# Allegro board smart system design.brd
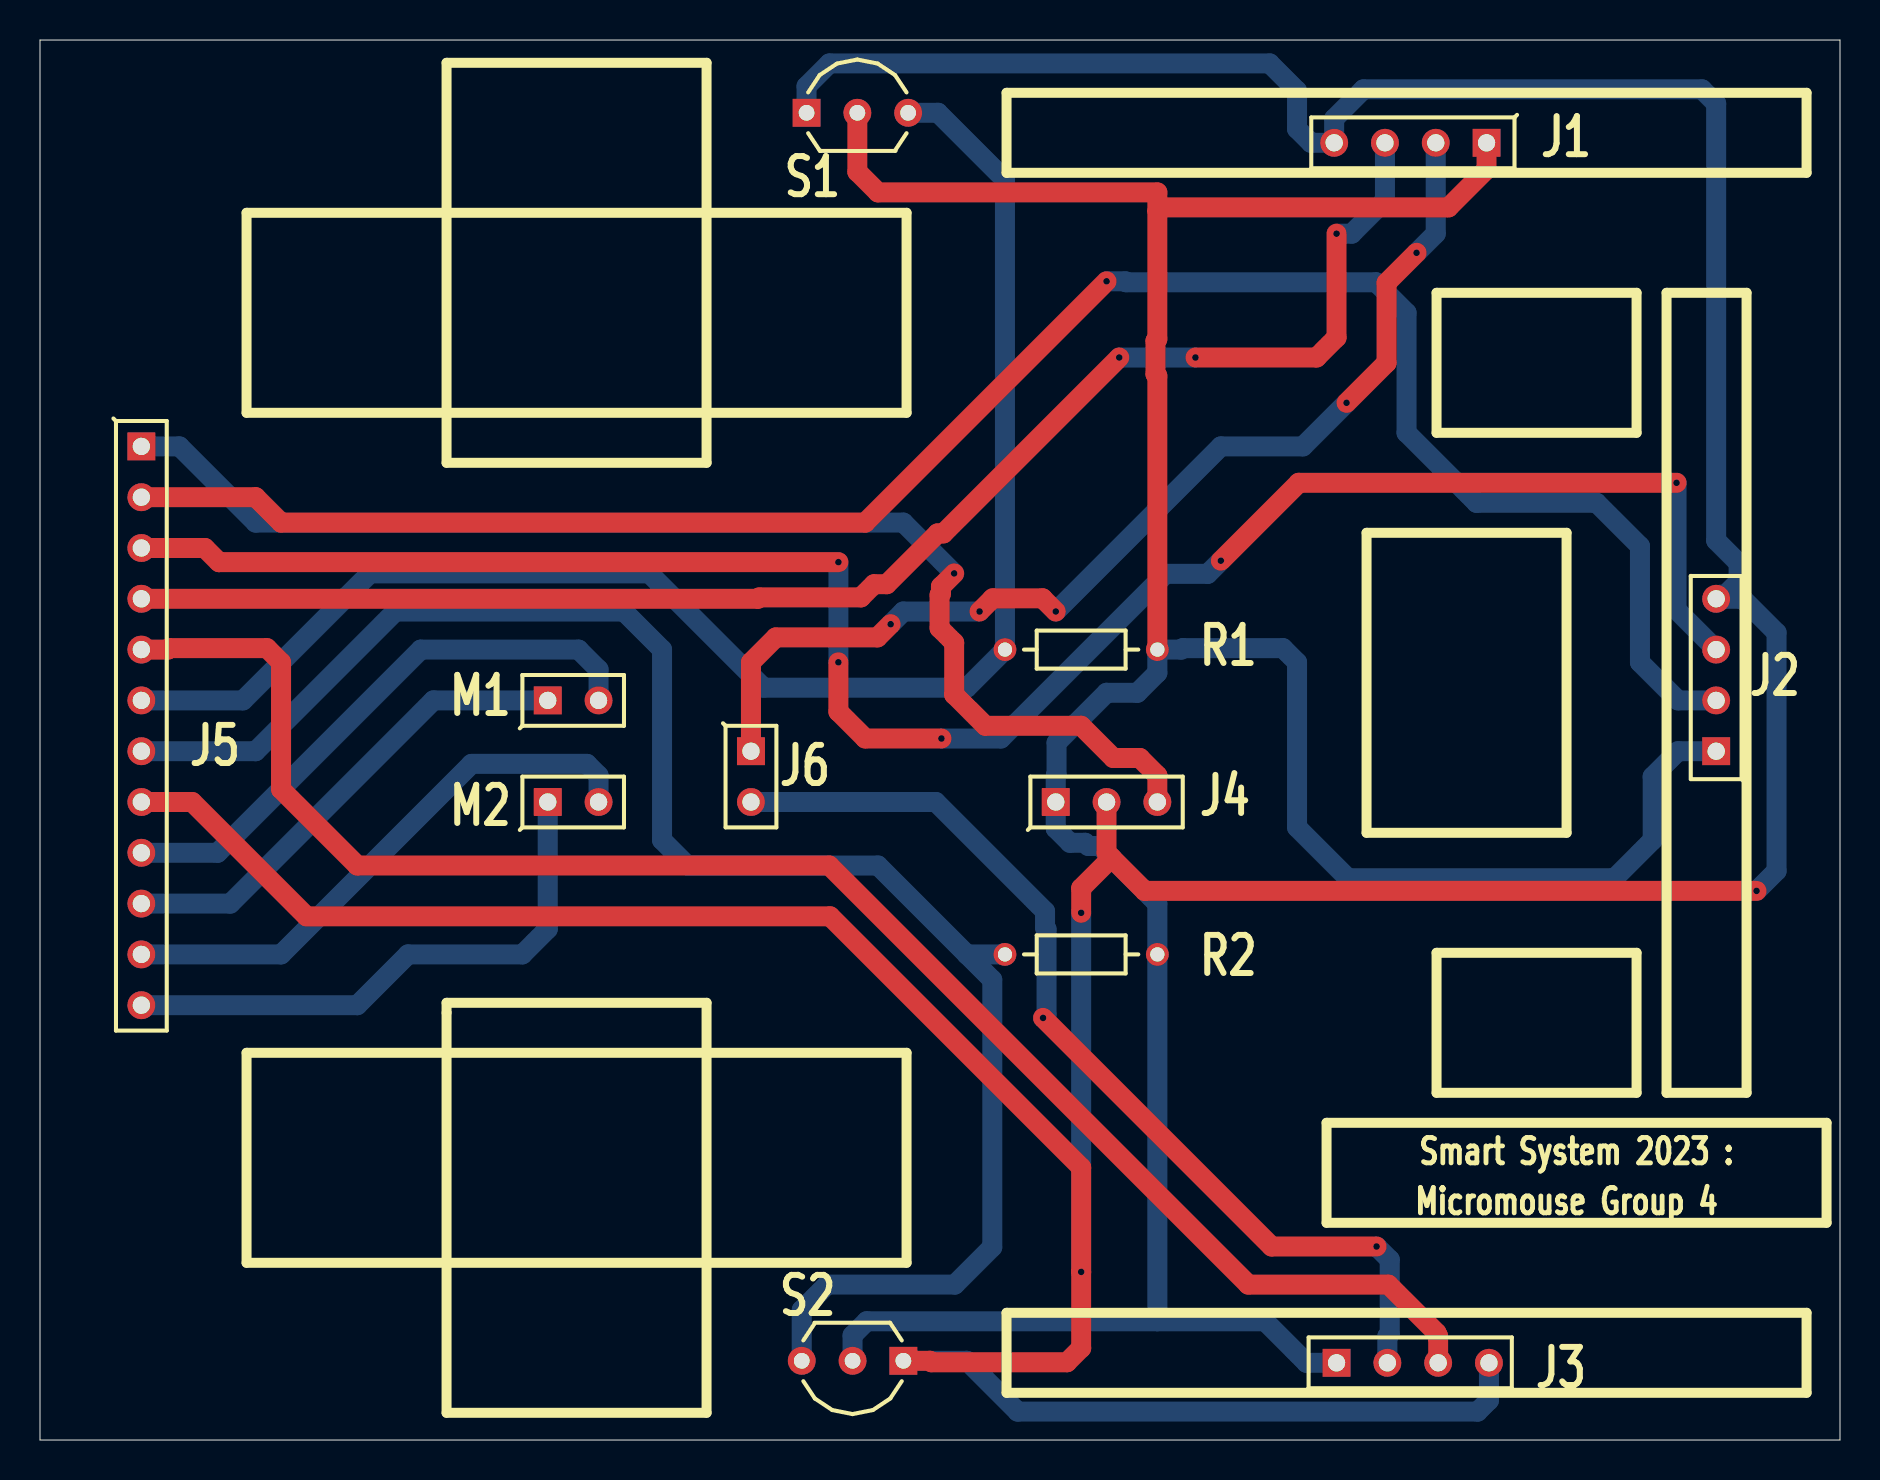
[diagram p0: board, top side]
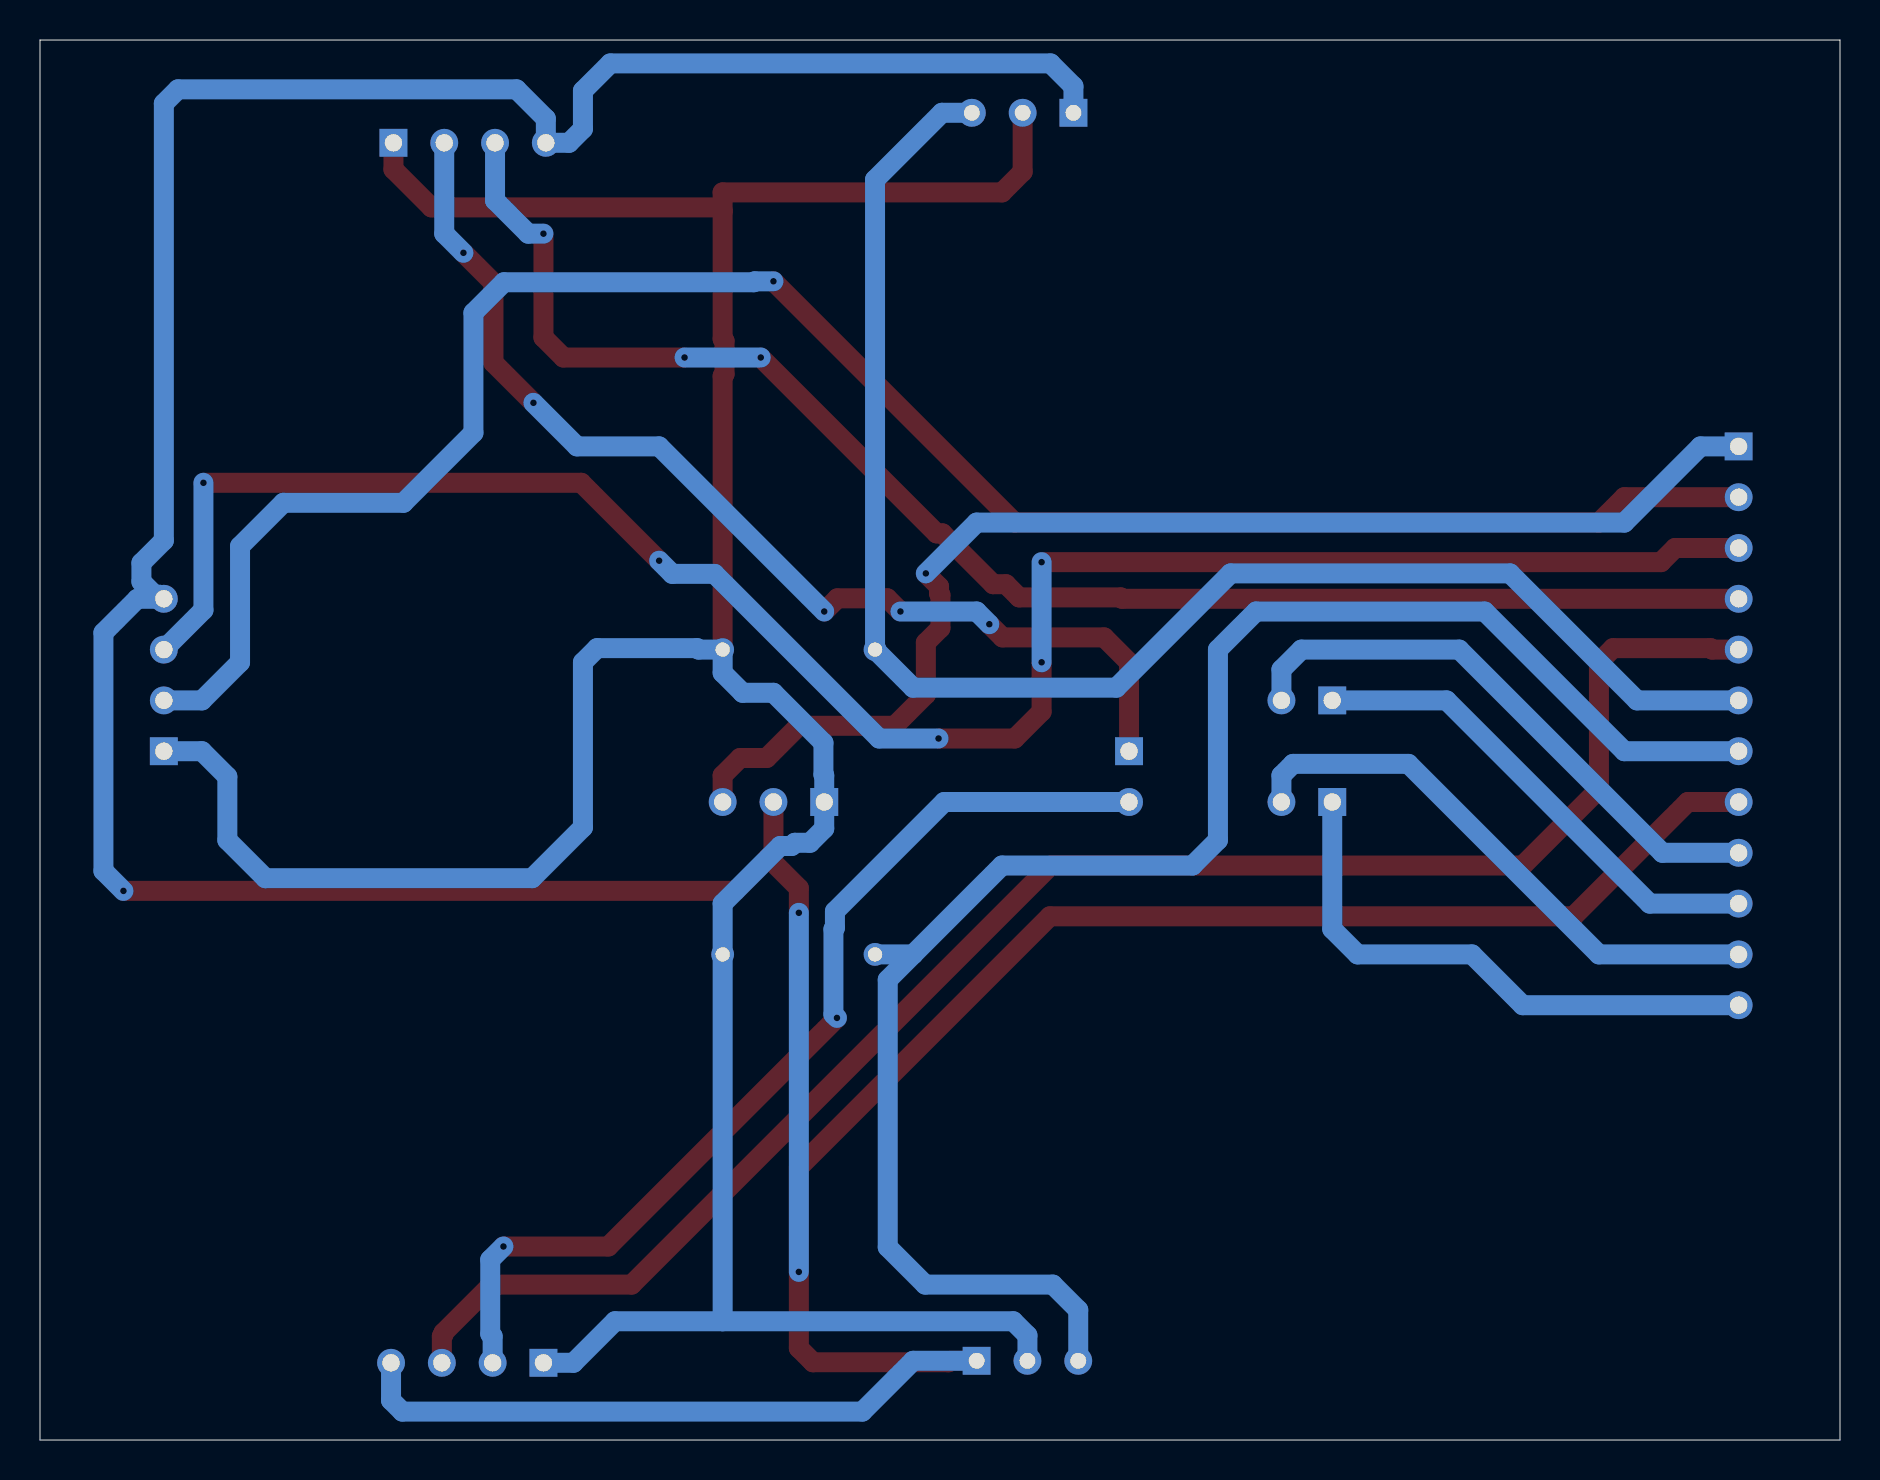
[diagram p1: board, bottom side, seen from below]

Outline 90 x 70 mm; copper layers: TOP, BOTTOM. Coordinates in mm from the lower left corner of the outline.
Outline path: 0,70 0,0 90,0 90,70 0,70

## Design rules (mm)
constraint set DEFAULT: min track width 0.127

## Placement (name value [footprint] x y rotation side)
J1  HEADER 4  [SIPTML4004]  72.33 64.86 180 top
J2  HEADER 4  [SIPTML4004]  83.81 34.44 90 top
J3  HEADER 4  [SIPTML4004]  64.83 3.86 0 top
J4  HEADER 3  [SIPTML3003]  50.79 31.9 0 top
J5  HEADER 12  [SIPTML120012]  5.07 49.68 270 top
J6  HEADER 2  [SIPTML2002]  35.55 34.44 270 top
M1  HEADER 2  [SIPTML2002]  25.39 36.98 0 top
M2  HEADER 2  [SIPTML2002]  25.39 31.9 0 top
R1  1k  [AXRC05]  48.25 39.52 0 top
R2  1k  [AXRC05]  55.87 24.28 180 top
S1  BC264A  [TO92100]  38.33 66.36 0 top
S2  BC264A  [TO92100]  43.17 3.96 180 top

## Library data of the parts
J1-J3 = HEADER 4
J4 = HEADER 3
J5 = HEADER 12
J6 M1 M2 = HEADER 2
R1 R2 = R
S1 S2 = BC264A

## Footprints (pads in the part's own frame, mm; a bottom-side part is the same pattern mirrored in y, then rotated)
AXRC05
  round 1.143 hole 0.711: 1(0,0) 2(7.62,0)
SIPTML2002
  rect 1.397x1.397 hole 0.864: 1(0,0)
  round 1.397 hole 0.864: 2(2.54,0)
SIPTML3003
  rect 1.397x1.397 hole 0.864: 1(0,0)
  round 1.397 hole 0.864: 2(2.54,0) 3(5.08,0)
SIPTML4004
  rect 1.397x1.397 hole 0.864: 1(0,0)
  round 1.397 hole 0.864: 2(2.54,0) 3(5.08,0) 4(7.62,0)
SIPTML120012
  rect 1.397x1.397 hole 0.864: 1(0,0)
  round 1.397 hole 0.864: 2(2.54,0) 3(5.08,0) 4(7.62,0) 5(10.16,0) 6(12.7,0) 7(15.24,0) 8(17.78,0) 9(20.32,0) 10(22.86,0) 11(25.4,0) 12(27.94,0)
TO92100
  rect 1.397x1.397 hole 0.787: 1(0,0)
  round 1.397 hole 0.787: 2(2.54,0) 3(5.08,0)

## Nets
N00360: J4.3 J5.1
N00369: J1.4 J2.4 J3.4 J4.2 J5.8 S1.1 S2.1
N00376: J1.1 J2.1 J3.1 J4.1 R1.2 R2.1 S1.2(S) S2.2(S)
N00451: J2.2 J5.2
N00455: J2.3 J5.3
N00470: J1.3 J5.4
N00474: J3.3 J5.5
N00833: J1.2 J6.1
N02519: J5.9 M1.2
N02528: J5.10 M1.1
N02537: J5.11 M2.2
N02546: J5.12 M2.1
N03250: J5.7 R2.2 S2.3
N03273: J5.6 R1.1 S1.3
N04280: J3.2 J6.2

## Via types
v1: diameter 0.61, hole 0.33, TOP to BOTTOM, 20 vias

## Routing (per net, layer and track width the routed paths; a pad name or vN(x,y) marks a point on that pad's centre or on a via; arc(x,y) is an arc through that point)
N00360: length 63.1
  TOP w1: v1(45.71,43.33) 45.05,42.67 45.05,42.32 44.98,42.25 44.98,40.6 45.71,39.87 45.71,37.27 47.27,35.71 52.06,35.71 53.67,34.1 55,34.1 55.87,33.23 J4.3
  BOTTOM w1: J5.1 6.97,49.68 10.78,45.87 43.17,45.87 v1(45.71,43.33)
N00369: length 257.5
  TOP w1: 53.58,29.11 52.06,27.59 v1(52.06,26.36) ; 53.58,29.11 55.23,27.46 v1(85.83,27.46) ; 53.58,29.11 53.33,29.36 J4.2 ; S2.1 44.5,3.96 44.57,3.89 51.35,3.89 52.06,4.6 v1(52.06,8.41) 52.06,13.63 39.5,26.19 13.32,26.19 7.61,31.9 J5.8
  BOTTOM w1: J3.4 72.45,1.99 71.88,1.42 48.88,1.42 46.34,3.96 S2.1 ; v1(85.83,27.46) 86.83,28.46 86.83,40.37 85.13,42.06 J2.4 84.01,42.26 84.27,42.26 84.93,42.92 84.93,43.85 83.81,44.97 83.81,66.82 83.1,67.53 66.17,67.53 64.71,66.07 J1.4 63.55,64.86 62.85,65.56 62.85,67.46 61.48,68.83 39.47,68.83 38.33,67.69 S1.1 ; v1(52.06,8.41) v1(52.06,26.36)
N00376: length 168.2
  TOP w1: 55.87,61.45 56.05,61.63 70.43,61.63 72.33,63.53 J1.1 72.33,64.92 ; 55.87,61.45 55.87,62.38 41.9,62.38 40.87,63.41 S1.2 ; 55.87,61.45 55.87,55.05 55.77,54.95 55.77,53.3 55.87,53.2 R1.2
  BOTTOM w1: J2.1 81.9,34.44 80.63,33.17 80.63,30 78.73,28.09 65.39,28.09 62.85,30.63 62.85,38.88 62.15,39.59 57.14,39.59 57.07,39.52 R1.2 55.87,38.36 54.87,37.36 53.33,37.36 50.83,34.86 50.83,33.27 50.79,33.23 J4.1 50.79,30.57 51.5,29.86 52.26,29.86 52.42,29.7 52.99,29.7 55.87,26.82 R2.1 55.87,5.94 ; S2.2 40.63,5.23 41.34,5.94 55.87,5.94 ; J3.1 63.33,3.86 61.25,5.94 55.87,5.94
N00451: length 99.9
  TOP w1: J5.2 10.78,47.14 12.05,45.87 41.26,45.87 v1(53.33,57.94)
  BOTTOM w1: v1(53.33,57.94) 54.26,57.94 54.31,57.89 66.8,57.89 68.33,56.36 68.33,50.36 71.83,46.86 77.83,46.86 80,44.69 80,38.88 81.9,36.98 J2.2
N00455: length 99.5
  TOP w1: v1(39.92,38.88) 39.92,36.42 41.26,35.07 v1(45.07,35.07) ; v1(39.92,43.89) 8.95,43.89 8.24,44.6 J5.3 ; v1(81.83,47.86) 62.94,47.86 v1(59.04,43.97)
  BOTTOM w1: v1(45.07,35.07) 48.04,35.07 56.27,43.31 58.38,43.31 v1(59.04,43.97) ; J2.3 81.83,41.5 v1(81.83,47.86) ; v1(39.92,43.89) v1(39.92,38.88)
N00470: length 76.4
  TOP w1: J5.4 35.89,42.06 35.96,42.13 41.04,42.13 41.7,42.79 42.34,42.79 44.88,45.33 45.17,45.33 v1(53.96,54.12) ; v1(57.77,54.12) 63.83,54.12 64.83,55.12 v1(64.83,60.32)
  BOTTOM w1: v1(64.83,60.32) 65.59,60.32 67.25,61.98 J1.3 ; v1(53.96,54.12) v1(57.77,54.12)
N00474: length 84.2
  TOP w1: J3.3 69.91,5.19 69.83,5.27 69.83,5.36 67.42,7.77 60.42,7.77 39.46,28.73 15.86,28.73 12.05,32.54 12.05,38.88 11.34,39.59 6.47,39.59 6.39,39.52 J5.5
N00833: length 55
  TOP w1: v1(65.33,51.86) 67.33,53.86 67.33,57.86 v1(68.83,59.36) ; v1(42.53,40.79) 41.87,40.13 36.79,40.13 35.55,38.88 J6.1 ; v1(46.98,41.43) 47.64,42.09 50.13,42.09 v1(50.79,41.43)
  BOTTOM w1: v1(42.53,40.79) 43.17,41.43 v1(46.98,41.43) ; v1(68.83,59.36) 69.79,60.32 J1.2 ; v1(50.79,41.43) 59.04,49.68 63.15,49.68 v1(65.33,51.86)
N02519: length 29
  BOTTOM w1: M1.2 27.93,38.52 26.93,39.52 19.04,39.52 8.88,29.36 J5.9
N02528: length 24.5
  BOTTOM w1: J5.10 9.51,26.82 19.67,36.98 M1.1
N02537: length 28.4
  BOTTOM w1: M2.2 27.93,33.23 27.35,33.81 21.58,33.81 12.05,24.28 J5.11
N02546: length 28.2
  BOTTOM w1: J5.12 15.86,21.74 18.4,24.28 24.12,24.28 25.39,25.55 M2.1
N03250: length 87.3
  BOTTOM w1: J5.7 10.78,34.44 17.77,41.43 29.2,41.43 31.1,39.52 31.1,30 32.37,28.73 41.9,28.73 46.34,24.28 ; 46.34,24.28 R2.2 ; 46.34,24.28 47.61,23.01 47.61,9.65 45.74,7.77 39.36,7.77 38.09,6.5 S2.3
N03273: length 78.7
  BOTTOM w1: S1.3 44.9,66.36 48.25,63.01 R1.1 46.34,37.62 36.18,37.62 30.47,43.33 16.5,43.33 10.15,36.98 J5.6
N04280: length 49.9
  TOP w1: v1(66.83,9.68) 61.58,9.68 v1(50.15,21.11)
  BOTTOM w1: J6.2 44.79,31.9 50.25,26.44 50.25,25.61 50.33,25.54 50.33,21.28 v1(50.15,21.11) ; J3.2 67.37,5.19 67.49,5.31 67.49,9.01 v1(66.83,9.68)

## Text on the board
Ref Des/Silkscreen Top: Micromouse Group 4 | Smart System 2023 :
